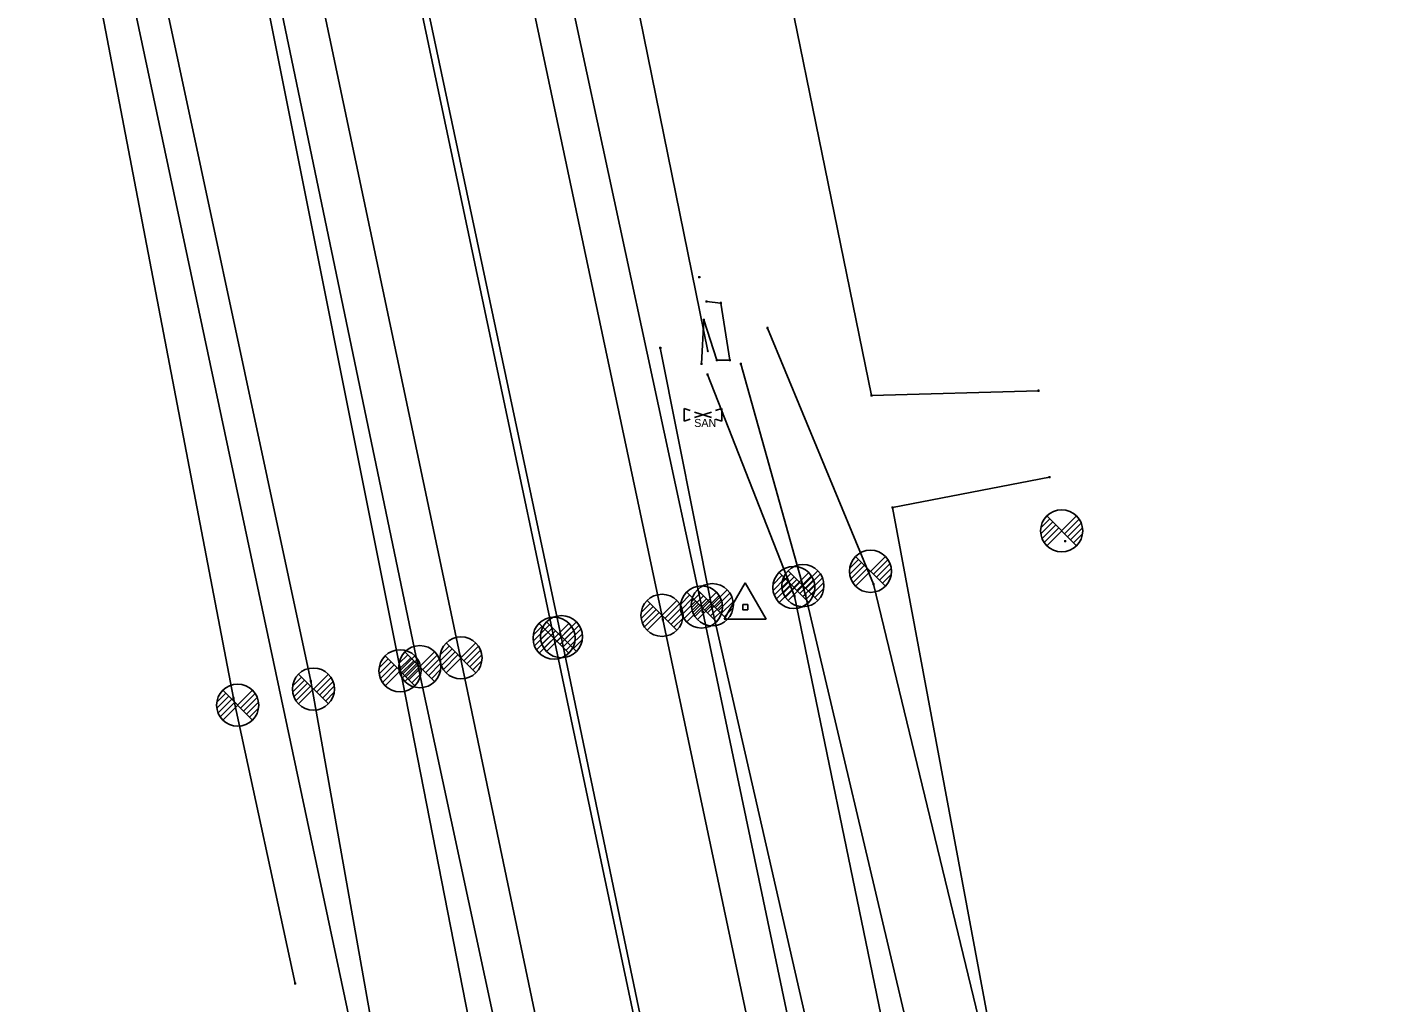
# Model space of a CAD drawing. Extents: x 1954856 to 2011933, y 399149 to 426294.
# Drawn here: x 2005368.5 to 2005528.8, y 405880.7 to 405996.6 of the extents above; entities that cross this region are included whole.
import ezdxf

# ---------------------------------------------------------------- set-up
doc = ezdxf.new("R2010")
doc.units = 0
for name, color, linetype in [('BankMent_ep', 7, 'Continuous'), ('BaselineSurvey', 7, 'Continuous'), ('ElecAer_ep', 7, 'Continuous'), ('EndTreatMES_ep', 7, 'Continuous'), ('Fence_ep', 7, 'Continuous'), ('FlowLineInvert_ep', 7, 'Continuous'), ('MonumentNL_ep', 7, 'Continuous'), ('PavtAsphalt_ep', 7, 'Continuous'), ('PavtAsphaltCrown_ep', 7, 'Continuous'), ('PipeCulvert_ep', 7, 'Continuous'), ('PointLocator_ep', 7, 'Continuous'), ('ShldrPaved_ep', 7, 'Continuous'), ('TreeLineScatter_ep', 7, 'Continuous'), ('ValveSewer_ep', 7, 'Continuous'), ('XSPt_ep', 7, 'Continuous')]:
    doc.layers.add(name, color=color, linetype=linetype)

msp = doc.modelspace()

# ---------------------------------------------------------------- linework, layer by layer
at = {"layer": 'BankMent_ep'}
for p, q in [((2005412.76, 405920.6), (2005393.12, 406018.84)), ((2005456.42, 405960.84), (2005469.02, 405930.44)), ((2005449.83, 405927.71), (2005443.7, 405958.48)), ((2005471.96, 405830.7), (2005449.83, 405927.71)), ((2005423.61, 405865.31), (2005412.76, 405920.6))]:
    msp.add_line(p, q, dxfattribs=at)
for points in [[(2005400.35, 405883.04), (2005393.03, 405916.92), (2005374.24, 406015.03)], [(2005414.34, 405850.78), (2005402.21, 405918.91), (2005381.35, 406016.35)], [(2005487.14, 405803.52), (2005483.65, 405832.94), (2005460.95, 405929.13), (2005453.25, 405956.6)], [(2005484.36, 405802.69), (2005479.66, 405832.02), (2005459.64, 405929.03), (2005449.31, 405955.32)], [(2005490.05, 405795.91), (2005499.22, 405797.5), (2005492.14, 405835.02), (2005469.02, 405930.44)]]:
    msp.add_lwpolyline(points, dxfattribs=at)
at = {"layer": 'BaselineSurvey'}
msp.add_line((2006223.92, 402174.38), (2005094.48, 407516.05), dxfattribs=at)
msp.add_line((2006223.92, 402174.38), (2005094.48, 407516.05), dxfattribs=at)
at = {"layer": 'ElecAer_ep'}
msp.add_lwpolyline([(2005445.5, 405696.72), (2005374.4, 406031.29), (2005427.33, 406130.78), (2005454.7, 406142.24)], dxfattribs=at)
at = {"layer": 'EndTreatMES_ep'}
msp.add_lwpolyline([(2005448.61, 405956.6), (2005448.89, 405961.82), (2005450.4, 405957.02), (2005451.95, 405957.01), (2005450.9, 405963.8), (2005449.19, 405964)], dxfattribs=at)
at = {"layer": 'Fence_ep'}
msp.add_lwpolyline([(2005488.61, 405953.4), (2005468.8, 405952.83), (2005452.99, 406030.1)], dxfattribs=at)
at = {"layer": 'FlowLineInvert_ep'}
for p, q in [((2005449.44, 405958.01), (2005449.26, 405958.18)), ((2005449.44, 405958.18), (2005449.26, 405958.01)), ((2005449.35, 405958.09), (2005449.35, 405958.09))]:
    msp.add_line(p, q, dxfattribs=at)
at = {"layer": 'MonumentNL_ep'}
for p, q in [((2005451.29, 405926.27), (2005453.79, 405930.6)), ((2005453.79, 405930.6), (2005456.29, 405926.27)), ((2005453.79, 405927.71), (2005453.79, 405927.71)), ((2005451.29, 405926.27), (2005456.29, 405926.27))]:
    msp.add_line(p, q, dxfattribs=at)
msp.add_lwpolyline([(2005453.49, 405928.01), (2005454.09, 405928.01), (2005454.09, 405927.41), (2005453.49, 405927.41)], close=True, dxfattribs=at)
at = {"layer": 'PavtAsphalt_ep'}
for points in [[(2005671.31, 404850.41), (2005650.51, 404948.22), (2005629.89, 405046.05), (2005609.27, 405144), (2005588.25, 405241.94), (2005567.84, 405339), (2005547.04, 405437.09), (2005526.5, 405535.12), (2005505.87, 405632.57), (2005485.22, 405730.46), (2005464.5, 405829.38), (2005444, 405926.25), (2005423.25, 406024.1)], [(2005647.53, 404845.36), (2005626.42, 404943.28), (2005605.83, 405041.29), (2005585.16, 405139.3), (2005564.57, 405237.07), (2005543.61, 405334.99), (2005527.25, 405416.17), (2005502.47, 405530.37), (2005481.58, 405628.35), (2005460.91, 405726.6), (2005440.43, 405824.02), (2005419.93, 405921.9), (2005399.29, 406019.76)]]:
    msp.add_lwpolyline(points, dxfattribs=at)
at = {"layer": 'PavtAsphaltCrown_ep'}
msp.add_lwpolyline([(2005659.53, 404847.95), (2005638.67, 404945.7), (2005617.91, 405043.69), (2005597.24, 405141.46), (2005576.51, 405239.3), (2005555.95, 405336.92), (2005535.17, 405434.82), (2005514.41, 405532.8), (2005493.56, 405630.59), (2005473.23, 405728.59), (2005452.36, 405826.42), (2005431.94, 405924.2), (2005411.14, 406022.06)], dxfattribs=at)
at = {"layer": 'PipeCulvert_ep'}
msp.add_lwpolyline([(2005449.35, 405958.09), (2005438.41, 406011.82)], dxfattribs=at)
at = {"layer": 'PointLocator_ep'}
for p, q in [((2005448.33, 405966.75), (2005448.33, 405967)), ((2005448.46, 405966.87), (2005448.21, 405966.87)), ((2005448.33, 405966.87), (2005448.33, 405966.87)), ((2005449.32, 405964), (2005449.07, 405964)), ((2005449.19, 405963.87), (2005449.19, 405964.12)), ((2005449.19, 405964), (2005449.19, 405964)), ((2005451.02, 405963.8), (2005450.77, 405963.8)), ((2005450.9, 405963.68), (2005450.9, 405963.93)), ((2005450.9, 405963.8), (2005450.9, 405963.8)), ((2005449.01, 405961.82), (2005448.76, 405961.82)), ((2005448.89, 405961.69), (2005448.89, 405961.94)), ((2005448.89, 405961.82), (2005448.89, 405961.82)), ((2005456.55, 405960.84), (2005456.3, 405960.84)), ((2005456.42, 405960.72), (2005456.42, 405960.97)), ((2005456.42, 405960.84), (2005456.42, 405960.84)), ((2005443.83, 405958.48), (2005443.58, 405958.48)), ((2005443.7, 405958.35), (2005443.7, 405958.6)), ((2005443.7, 405958.48), (2005443.7, 405958.48)), ((2005448.73, 405956.6), (2005448.48, 405956.6)), ((2005448.61, 405956.47), (2005448.61, 405956.72)), ((2005448.61, 405956.6), (2005448.61, 405956.6)), ((2005450.53, 405957.02), (2005450.28, 405957.02)), ((2005450.4, 405956.89), (2005450.4, 405957.14)), ((2005450.4, 405957.02), (2005450.4, 405957.02)), ((2005452.08, 405957.01), (2005451.83, 405957.01)), ((2005451.95, 405956.89), (2005451.95, 405957.14)), ((2005451.95, 405957.01), (2005451.95, 405957.01)), ((2005453.38, 405956.6), (2005453.13, 405956.6)), ((2005453.25, 405956.47), (2005453.25, 405956.72)), ((2005453.25, 405956.6), (2005453.25, 405956.6)), ((2005449.43, 405955.32), (2005449.18, 405955.32)), ((2005449.31, 405955.19), (2005449.31, 405955.44)), ((2005449.31, 405955.32), (2005449.31, 405955.32)), ((2005468.92, 405952.83), (2005468.67, 405952.83)), ((2005468.8, 405952.7), (2005468.8, 405952.95)), ((2005468.8, 405952.83), (2005468.8, 405952.83)), ((2005488.74, 405953.4), (2005488.49, 405953.4)), ((2005488.61, 405953.28), (2005488.61, 405953.53)), ((2005488.61, 405953.4), (2005488.61, 405953.4)), ((2005490.04, 405943.13), (2005489.79, 405943.13)), ((2005489.91, 405943.01), (2005489.91, 405943.26)), ((2005489.91, 405943.13), (2005489.91, 405943.13)), ((2005471.39, 405939.53), (2005471.14, 405939.53)), ((2005471.26, 405939.41), (2005471.26, 405939.66)), ((2005471.26, 405939.53), (2005471.26, 405939.53)), ((2005491.89, 405935.53), (2005491.64, 405935.53)), ((2005491.77, 405935.41), (2005491.77, 405935.66)), ((2005491.77, 405935.53), (2005491.77, 405935.53)), ((2005469.15, 405930.44), (2005468.9, 405930.44)), ((2005469.02, 405930.32), (2005469.02, 405930.57)), ((2005469.02, 405930.44), (2005469.02, 405930.44)), ((2005459.77, 405929.03), (2005459.52, 405929.03)), ((2005459.64, 405928.91), (2005459.64, 405929.16)), ((2005459.64, 405929.03), (2005459.64, 405929.03)), ((2005461.08, 405929.13), (2005460.83, 405929.13)), ((2005460.95, 405929.01), (2005460.95, 405929.26)), ((2005460.95, 405929.13), (2005460.95, 405929.13)), ((2005448.86, 405927.16), (2005448.61, 405927.16)), ((2005448.74, 405927.04), (2005448.74, 405927.29)), ((2005448.74, 405927.16), (2005448.74, 405927.16)), ((2005449.96, 405927.71), (2005449.71, 405927.71)), ((2005449.83, 405927.59), (2005449.83, 405927.84)), ((2005449.83, 405927.71), (2005449.83, 405927.71)), ((2005444.13, 405926.25), (2005443.88, 405926.25)), ((2005444, 405926.13), (2005444, 405926.38)), ((2005444, 405926.25), (2005444, 405926.25)), ((2005432.06, 405924.2), (2005431.81, 405924.2)), ((2005431.94, 405924.07), (2005431.94, 405924.32)), ((2005431.94, 405924.2), (2005431.94, 405924.2)), ((2005412.89, 405920.6), (2005412.64, 405920.6)), ((2005412.76, 405920.47), (2005412.76, 405920.72)), ((2005412.76, 405920.6), (2005412.76, 405920.6)), ((2005414.98, 405921.03), (2005414.73, 405921.03)), ((2005414.86, 405920.91), (2005414.86, 405921.16)), ((2005414.86, 405921.03), (2005414.86, 405921.03)), ((2005420.05, 405921.9), (2005419.8, 405921.9)), ((2005419.93, 405921.78), (2005419.93, 405922.03)), ((2005419.93, 405921.9), (2005419.93, 405921.9)), ((2005402.34, 405918.91), (2005402.09, 405918.91)), ((2005402.21, 405918.78), (2005402.21, 405919.03)), ((2005402.21, 405918.91), (2005402.21, 405918.91)), ((2005393.16, 405916.92), (2005392.91, 405916.92)), ((2005393.03, 405916.8), (2005393.03, 405917.05)), ((2005393.03, 405916.92), (2005393.03, 405916.92)), ((2005400.48, 405883.04), (2005400.23, 405883.04)), ((2005400.35, 405882.91), (2005400.35, 405883.16)), ((2005400.35, 405883.04), (2005400.35, 405883.04))]:
    msp.add_line(p, q, dxfattribs=at)
at = {"layer": 'ShldrPaved_ep'}
for points in [[(2005661.01, 404921.05), (2005655.38, 404949.38), (2005634.67, 405046.77), (2005613.98, 405144.94), (2005594.72, 405236.59), (2005590.09, 405258.66), (2005572.53, 405339.95), (2005551.67, 405437.94), (2005530.81, 405538.07), (2005522.22, 405579.31), (2005511, 405633.61), (2005501.96, 405674.37), (2005495.79, 405704.21), (2005482.81, 405765.83), (2005476.98, 405793.67), (2005469.08, 405830.21), (2005448.74, 405927.16), (2005427.7, 406024.97)], [(2005642.79, 404844.43), (2005626.09, 404922.97), (2005619.59, 404953.5), (2005603.98, 405028.2), (2005595.2, 405068.87), (2005580.62, 405138.25), (2005559.73, 405235.86), (2005538.96, 405333.93), (2005522.84, 405410.17), (2005520.12, 405422.33), (2005518.17, 405431.54), (2005497.8, 405529.43), (2005476.92, 405627.44), (2005463.13, 405692.8), (2005451.37, 405749.13), (2005441.12, 405797.5), (2005431.89, 405841.86), (2005414.86, 405921.03), (2005394.47, 406019.03)]]:
    msp.add_lwpolyline(points, dxfattribs=at)
at = {"layer": 'TreeLineScatter_ep'}
msp.add_lwpolyline([(2005495.65, 405808.94), (2005471.26, 405939.53), (2005489.91, 405943.13)], dxfattribs=at)
at = {"layer": 'ValveSewer_ep'}
for p, q in [((2005447.27, 405951.04), (2005446.52, 405951.29)), ((2005446.52, 405949.79), (2005446.52, 405951.29)), ((2005450.27, 405951.04), (2005451.02, 405951.29)), ((2005451.02, 405951.29), (2005451.02, 405949.79)), ((2005446.52, 405949.79), (2005447.27, 405950.04)), ((2005449.77, 405950.21), (2005447.77, 405950.87)), ((2005447.77, 405950.21), (2005449.77, 405950.87)), ((2005448.77, 405950.54), (2005448.77, 405950.54)), ((2005451.02, 405949.79), (2005450.27, 405950.04))]:
    msp.add_line(p, q, dxfattribs=at)
at = {"layer": 'XSPt_ep'}
for p, q in [((2005488.88, 405937.12), (2005489.94, 405938.18)), ((2005489.59, 405935), (2005493.13, 405938.54)), ((2005493.13, 405935), (2005489.59, 405938.54)), ((2005491.71, 405936.41), (2005493.44, 405938.15)), ((2005488.88, 405936.41), (2005490.3, 405937.83)), ((2005489.03, 405935.85), (2005490.65, 405937.48)), ((2005489.27, 405935.39), (2005491.01, 405937.12)), ((2005491.36, 405936.77), (2005491.36, 405936.77)), ((2005492.07, 405936.06), (2005493.69, 405937.68)), ((2005492.42, 405935.71), (2005493.83, 405937.12)), ((2005492.77, 405935.35), (2005493.83, 405936.41)), ((2005466.19, 405932.32), (2005467.25, 405933.38)), ((2005466.89, 405930.2), (2005470.43, 405933.74)), ((2005470.43, 405930.2), (2005466.89, 405933.74)), ((2005469.01, 405931.62), (2005470.75, 405933.35)), ((2005457.8, 405928.28), (2005461.33, 405931.81)), ((2005461.33, 405928.28), (2005457.8, 405931.81)), ((2005458.16, 405930.63), (2005459.22, 405931.69)), ((2005458.87, 405928.51), (2005462.41, 405932.04)), ((2005462.41, 405928.51), (2005458.87, 405932.04)), ((2005466.19, 405931.62), (2005467.6, 405933.03)), ((2005466.33, 405931.06), (2005467.95, 405932.68)), ((2005466.58, 405930.59), (2005468.31, 405932.32)), ((2005468.66, 405931.97), (2005468.66, 405931.97)), ((2005469.37, 405931.26), (2005470.99, 405932.88)), ((2005469.72, 405930.91), (2005471.14, 405932.32)), ((2005457.09, 405930.4), (2005458.15, 405931.46)), ((2005457.09, 405929.69), (2005458.5, 405931.11)), ((2005457.24, 405929.13), (2005458.86, 405930.75)), ((2005457.48, 405928.67), (2005459.21, 405930.4)), ((2005458.16, 405929.92), (2005459.58, 405931.33)), ((2005458.31, 405929.36), (2005459.93, 405930.98)), ((2005458.55, 405928.89), (2005460.29, 405930.63)), ((2005459.92, 405929.69), (2005461.65, 405931.42)), ((2005460.27, 405929.34), (2005461.89, 405930.96)), ((2005460.62, 405928.98), (2005462.04, 405930.4)), ((2005460.64, 405930.27), (2005460.64, 405930.27)), ((2005460.99, 405929.92), (2005462.72, 405931.65)), ((2005461.35, 405929.57), (2005462.97, 405931.19)), ((2005461.7, 405929.21), (2005463.11, 405930.63)), ((2005470.08, 405930.55), (2005471.14, 405931.62)), ((2005442.14, 405924.97), (2005445.68, 405928.5)), ((2005445.68, 405924.97), (2005442.14, 405928.5)), ((2005446.13, 405928.08), (2005447.19, 405929.14)), ((2005446.13, 405927.37), (2005447.54, 405928.79)), ((2005446.84, 405925.96), (2005450.37, 405929.5)), ((2005450.37, 405925.96), (2005446.84, 405929.5)), ((2005447.4, 405928.35), (2005448.46, 405929.41)), ((2005447.4, 405927.64), (2005448.82, 405929.06)), ((2005447.55, 405927.08), (2005449.17, 405928.7)), ((2005448.11, 405926.23), (2005451.64, 405929.76)), ((2005451.64, 405926.23), (2005448.11, 405929.76)), ((2005448.96, 405927.37), (2005450.69, 405929.11)), ((2005449.31, 405927.02), (2005450.93, 405928.64)), ((2005450.23, 405927.64), (2005451.96, 405929.38)), ((2005450.58, 405927.29), (2005452.2, 405928.91)), ((2005459.56, 405930.05), (2005459.56, 405930.05)), ((2005460.98, 405928.63), (2005462.04, 405929.69)), ((2005462.05, 405928.86), (2005463.11, 405929.92)), ((2005441.43, 405927.09), (2005442.49, 405928.15)), ((2005441.43, 405926.38), (2005442.85, 405927.8)), ((2005441.58, 405925.82), (2005443.2, 405927.44)), ((2005441.82, 405925.36), (2005443.56, 405927.09)), ((2005444.26, 405926.38), (2005445.99, 405928.11)), ((2005444.62, 405926.03), (2005446.24, 405927.65)), ((2005444.97, 405925.67), (2005446.38, 405927.09)), ((2005446.28, 405926.81), (2005447.9, 405928.44)), ((2005446.52, 405926.35), (2005448.25, 405928.08)), ((2005447.79, 405926.62), (2005449.52, 405928.35)), ((2005448.6, 405927.73), (2005448.6, 405927.73)), ((2005449.67, 405926.67), (2005451.08, 405928.08)), ((2005449.88, 405928), (2005449.88, 405928)), ((2005450.02, 405926.31), (2005451.08, 405927.37)), ((2005450.94, 405926.94), (2005452.35, 405928.35)), ((2005451.29, 405926.58), (2005452.35, 405927.64)), ((2005428.62, 405924.38), (2005429.68, 405925.44)), ((2005429.32, 405922.26), (2005432.86, 405925.79)), ((2005432.86, 405922.26), (2005429.32, 405925.79)), ((2005429.5, 405924.56), (2005430.56, 405925.63)), ((2005429.5, 405923.86), (2005430.91, 405925.27)), ((2005430.2, 405922.44), (2005433.74, 405925.98)), ((2005433.74, 405922.44), (2005430.2, 405925.98)), ((2005431.45, 405923.67), (2005433.18, 405925.4)), ((2005432.33, 405923.86), (2005434.06, 405925.59)), ((2005443.91, 405926.74), (2005443.91, 405926.74)), ((2005445.32, 405925.32), (2005446.38, 405926.38)), ((2005428.62, 405923.67), (2005430.03, 405925.09)), ((2005428.76, 405923.11), (2005430.38, 405924.73)), ((2005429.01, 405922.65), (2005430.74, 405924.38)), ((2005429.64, 405923.3), (2005431.26, 405924.92)), ((2005429.89, 405922.83), (2005431.62, 405924.56)), ((2005431.09, 405924.03), (2005431.09, 405924.03)), ((2005431.8, 405923.32), (2005433.42, 405924.94)), ((2005431.97, 405924.21), (2005431.97, 405924.21)), ((2005432.15, 405922.96), (2005433.57, 405924.38)), ((2005432.51, 405922.61), (2005433.57, 405923.67)), ((2005432.68, 405923.5), (2005434.3, 405925.12)), ((2005433.03, 405923.15), (2005434.45, 405924.56)), ((2005433.39, 405922.8), (2005434.45, 405923.86)), ((2005412.67, 405921.01), (2005413.73, 405922.07)), ((2005413.38, 405918.89), (2005416.91, 405922.42)), ((2005416.91, 405918.89), (2005413.38, 405922.42)), ((2005417.56, 405922.04), (2005418.62, 405923.1)), ((2005417.56, 405921.33), (2005418.98, 405922.75)), ((2005417.71, 405920.77), (2005419.33, 405922.4)), ((2005418.27, 405919.92), (2005421.8, 405923.46)), ((2005421.8, 405919.92), (2005418.27, 405923.46)), ((2005420.39, 405921.33), (2005422.12, 405923.07)), ((2005420.74, 405920.98), (2005422.36, 405922.6)), ((2005410.32, 405920.51), (2005411.38, 405921.57)), ((2005410.32, 405919.8), (2005411.74, 405921.22)), ((2005410.47, 405919.24), (2005412.09, 405920.86)), ((2005410.71, 405918.78), (2005412.44, 405920.51)), ((2005411.03, 405918.39), (2005414.56, 405921.92)), ((2005414.56, 405918.39), (2005411.03, 405921.92)), ((2005412.67, 405920.3), (2005414.08, 405921.71)), ((2005412.82, 405919.74), (2005414.44, 405921.36)), ((2005413.06, 405919.27), (2005414.79, 405921.01)), ((2005413.15, 405919.8), (2005414.88, 405921.54)), ((2005413.5, 405919.45), (2005415.12, 405921.07)), ((2005413.86, 405919.1), (2005415.27, 405920.51)), ((2005415.15, 405920.65), (2005415.15, 405920.65)), ((2005415.5, 405920.3), (2005417.23, 405922.03)), ((2005415.85, 405919.95), (2005417.47, 405921.57)), ((2005416.21, 405919.59), (2005417.62, 405921.01)), ((2005417.95, 405920.31), (2005419.68, 405922.04)), ((2005420.04, 405921.69), (2005420.04, 405921.69)), ((2005421.1, 405920.63), (2005422.51, 405922.04)), ((2005421.45, 405920.27), (2005422.51, 405921.33)), ((2005400.05, 405918.34), (2005401.11, 405919.4)), ((2005400.05, 405917.63), (2005401.46, 405919.05)), ((2005400.76, 405916.22), (2005404.29, 405919.75)), ((2005404.29, 405916.22), (2005400.76, 405919.75)), ((2005402.88, 405917.63), (2005404.61, 405919.36)), ((2005403.23, 405917.28), (2005404.85, 405918.9)), ((2005412.8, 405920.16), (2005412.8, 405920.16)), ((2005414.21, 405918.74), (2005415.27, 405919.8)), ((2005416.56, 405919.24), (2005417.62, 405920.3)), ((2005391.05, 405916.44), (2005392.11, 405917.5)), ((2005391.76, 405914.31), (2005395.29, 405917.85)), ((2005395.29, 405914.31), (2005391.76, 405917.85)), ((2005393.88, 405915.73), (2005395.61, 405917.46)), ((2005400.2, 405917.07), (2005401.82, 405918.69)), ((2005400.44, 405916.61), (2005402.17, 405918.34)), ((2005402.52, 405917.99), (2005402.52, 405917.99)), ((2005403.58, 405916.92), (2005405, 405918.34)), ((2005403.94, 405916.57), (2005405, 405917.63)), ((2005391.05, 405915.73), (2005392.46, 405917.14)), ((2005391.2, 405915.17), (2005392.82, 405916.79)), ((2005391.44, 405914.7), (2005393.17, 405916.44)), ((2005393.52, 405916.08), (2005393.52, 405916.08)), ((2005394.23, 405915.37), (2005395.85, 405917)), ((2005394.58, 405915.02), (2005396, 405916.44)), ((2005394.94, 405914.67), (2005396, 405915.73))]:
    msp.add_line(p, q, dxfattribs=at)
for centre in [(2005491.36, 405936.77), (2005468.66, 405931.97), (2005459.56, 405930.05), (2005460.64, 405930.27), (2005448.6, 405927.73), (2005449.88, 405928), (2005443.91, 405926.74), (2005431.09, 405924.03), (2005431.97, 405924.21), (2005420.04, 405921.69), (2005412.8, 405920.16), (2005415.15, 405920.65), (2005402.52, 405917.99), (2005393.52, 405916.08)]:
    msp.add_circle(centre, 2.5, dxfattribs=at)

# ---------------------------------------------------------------- texts
at = {"layer": 'ValveSewer_ep'}
msp.add_text('SAN', height=0.95, dxfattribs=at).set_placement((2005447.73, 405949.1))

doc.saveas('drawing.dxf')
